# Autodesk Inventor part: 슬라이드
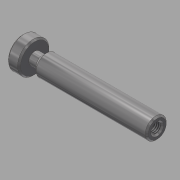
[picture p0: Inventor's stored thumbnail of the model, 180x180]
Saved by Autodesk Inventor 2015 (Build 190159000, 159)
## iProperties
Created: 2015-12
Part Number: 슬라이드
Document SubType Name: Modeling
Designer: mdu
Density: 8.08 g/cm^3
Material: 스테인리스강
Appearance: 반광택
Mass: 114.493 g
Surface Area: 49.8963 cm^2
Volume: 14.17 cm^3
Author: mdu
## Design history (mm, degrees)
sketch "스케치1"
  geometry: L1 (-45, 0)-(45, 0); L2 (-45, 0)-(-45, 10.5); L3 (-45, 10.5)-(-37, 10.5); L4 (-37, 10.5)-(-37, 4); L5 (-37, 4)-(-32, 4); L6 (-32, 4)-(-29, 7); L7 (-29, 7)-(45, 7); L8 (45, 7)-(45, 0); 2 further points
  constraints: 16 end point, 4 parallel, 2 perpendicular, 1 coincident, 1 horizontal, 1 midpoint
  dimensions: "d0" = 90 distance of L1.start L1.end; "d1" = 21 diameter of L3 L1; "d2" = 14 diameter of L7 L1; "d3" = 8 diameter of L5 L1; "d4" = 8 distance of L2.end L3.end; "d5" = 5 distance of L4.end L5.end; "d6" = 135 deg angle of L6 L5
revolve "회전1" sketch "스케치1" stored, may be unused: angle "d7" = 90 deg
chamfer "모따기1" distance "d8" = 1; stored, may be unused: second distance "d9" = 2, angle "d10" = 45 deg
hole "구멍1" diameter "d13" = 6.647; stored, may be unused: countersink angle "d17" = 90 deg, drill point angle "d19" = 118 deg; dims "d11" = 10, "d12" = 10, "d14" = 9, "d15" = 4, "d16" = 2, "d18" = 12
chamfer "모따기2" distance "d20" = 1; stored, may be unused: second distance "d21" = 2, angle "d22" = 45 deg
node "솔리드1"
